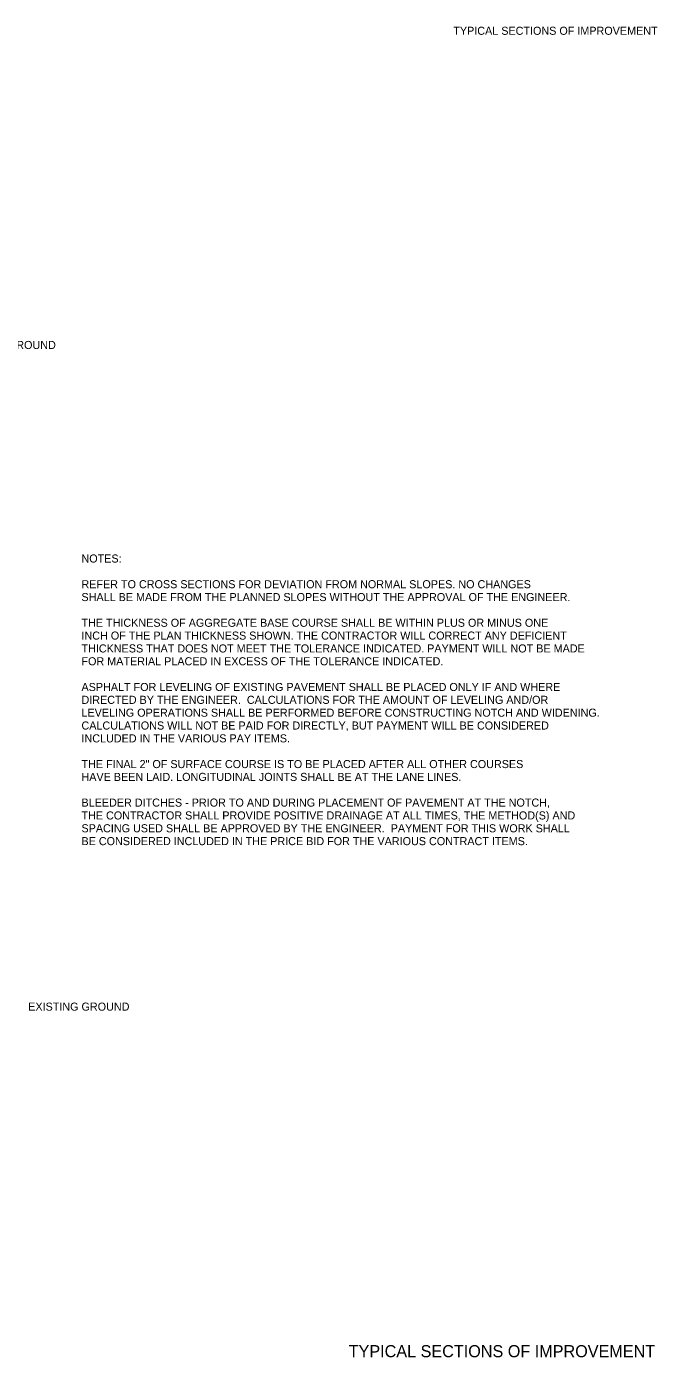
# Model space of a CAD drawing. Extents: x 1461570 to 1461697, y 1686711 to 1686957.
# Drawn here: x 1461650 to 1461697, y 1686710.9 to 1686809.9 of the extents above; entities that cross this region are included whole.
import ezdxf

# ---------------------------------------------------------------- set-up
doc = ezdxf.new("R2010")
doc.units = 0
for name, color, linetype in [('1', 7, 'Continuous'), ('G-ANNO-TEXT', 7, 'Continuous'), ('R_Draft', 7, 'Continuous')]:
    doc.layers.add(name, color=color, linetype=linetype)

msp = doc.modelspace()

# ---------------------------------------------------------------- texts
at = {"layer": '1'}
for s, p in [('NOTES:', (1461654.11, 1686770.017)), ('REFER TO CROSS SECTIONS FOR DEVIATION FROM NORMAL SLOPES. NO CHANGES', (1461654.11, 1686768.105)), ('SHALL BE MADE FROM THE PLANNED SLOPES WITHOUT THE APPROVAL OF THE ENGINEER.', (1461654.11, 1686767.149)), ('THE THICKNESS OF AGGREGATE BASE COURSE SHALL BE WITHIN PLUS OR MINUS ONE', (1461654.11, 1686765.238)), ('INCH OF THE PLAN THICKNESS SHOWN. THE CONTRACTOR WILL CORRECT ANY DEFICIENT', (1461654.11, 1686764.282)), ('THICKNESS THAT DOES NOT MEET THE TOLERANCE INDICATED. PAYMENT WILL NOT BE MADE', (1461654.11, 1686763.326)), ('FOR MATERIAL PLACED IN EXCESS OF THE TOLERANCE INDICATED.', (1461654.11, 1686762.37)), ('ASPHALT FOR LEVELING OF EXISTING PAVEMENT SHALL BE PLACED ONLY IF AND WHERE', (1461654.11, 1686760.458)), ('DIRECTED BY THE ENGINEER.  CALCULATIONS FOR THE AMOUNT OF LEVELING AND/OR ', (1461654.11, 1686759.502)), ('LEVELING OPERATIONS SHALL BE PERFORMED BEFORE CONSTRUCTING NOTCH AND WIDENING.', (1461654.11, 1686758.546)), ('CALCULATIONS WILL NOT BE PAID FOR DIRECTLY, BUT PAYMENT WILL BE CONSIDERED', (1461654.11, 1686757.59)), ('INCLUDED IN THE VARIOUS PAY ITEMS.', (1461654.11, 1686756.634)), ('THE FINAL 2" OF SURFACE COURSE IS TO BE PLACED AFTER ALL OTHER COURSES', (1461654.11, 1686754.722)), ('HAVE BEEN LAID. LONGITUDINAL JOINTS SHALL BE AT THE LANE LINES.', (1461654.11, 1686753.766)), ('BLEEDER DITCHES - PRIOR TO AND DURING PLACEMENT OF PAVEMENT AT THE NOTCH,', (1461654.11, 1686751.855)), ('THE CONTRACTOR SHALL PROVIDE POSITIVE DRAINAGE AT ALL TIMES, THE METHOD(S) AND', (1461654.11, 1686750.899)), ('SPACING USED SHALL BE APPROVED BY THE ENGINEER.  PAYMENT FOR THIS WORK SHALL', (1461654.11, 1686749.943)), ('BE CONSIDERED INCLUDED IN THE PRICE BID FOR THE VARIOUS CONTRACT ITEMS.', (1461654.11, 1686748.987))]:
    msp.add_text(s, height=0.6, dxfattribs=at).set_placement(p)
at = {"layer": 'G-ANNO-TEXT'}
for height, p in [(0.6, (1461681.775, 1686809.29)), (0.9, (1461673.991, 1686710.882))]:
    msp.add_text('TYPICAL SECTIONS OF IMPROVEMENT', height=height, dxfattribs=at).set_placement(p)
at = {"layer": 'R_Draft'}
for p in [(1461644.669, 1686785.909), (1461650.146, 1686736.671)]:
    msp.add_text('EXISTING GROUND', height=0.6, dxfattribs=at).set_placement(p)

doc.saveas('drawing.dxf')
